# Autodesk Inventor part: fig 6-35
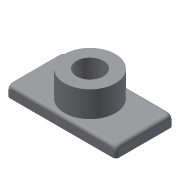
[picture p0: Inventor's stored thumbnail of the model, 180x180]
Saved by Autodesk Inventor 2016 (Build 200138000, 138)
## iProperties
Created: 2004-05
Part Number: fig 6-35
Document SubType Name: Modeling
Designer: CADCIM Technologies
Manufacturer: Standard
Standards Organization: Custom
Density: 1 g/cm^3
Material: Generic
Appearance: Default
Author: CADCIM Technologies
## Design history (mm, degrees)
sketch "Sketch1"
  geometry: L1 (-39.276, -18.692)-(33.721, -18.692); L2 (33.721, -18.692)-(33.721, 19.728); L3 (33.721, 19.728)-(-39.276, 19.728); L4 (-39.276, 19.728)-(-39.276, -18.692)
  constraints: 8 end point, 2 parallel, 1 horizontal, 1 perpendicular
extrude "Extrusion1" new body sketch "Sketch1" distance "d0" = 7.5; taper "d1" = 0 deg
sketch "Sketch2"
  geometry: C1 r 17 at (-2.778, 0.518)
  constraints: 1 centre point
  dimensions: "d16" = 34 diameter of C1
extrude "Extrusion2" join sketch "Sketch2" distance "d3" = 17.25; taper "d4" = 0 deg
hole "Hole1" diameter "d8" = 18; stored, may be unused: countersink angle "d12" = 90 deg, drill point angle "d14" = 118 deg; dims "d6" = 10, "d7" = 10, "d9" = 6, "d10" = 4, "d11" = 2, "d13" = 8
fillet "Fillet4" dims "d17" = 2
body "Solid1"
